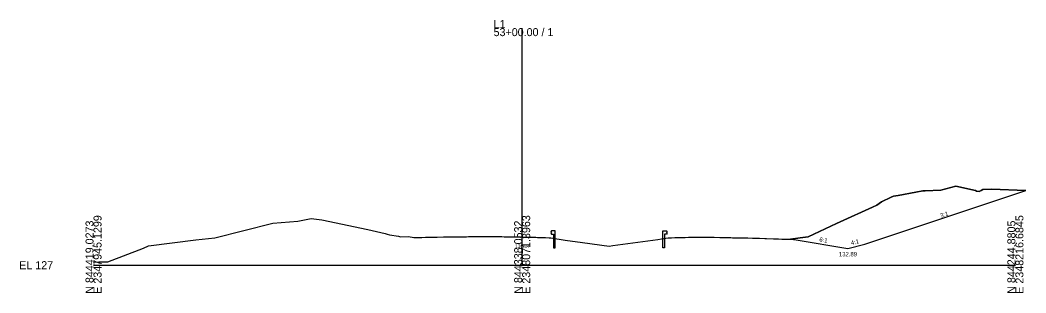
# Model space of a CAD drawing. Extents: x -26 to 2348258, y -10 to 844496.
# Drawn here: x 1275.5 to 1627.5, y 3990.3 to 4085.7 of the extents above; entities that cross this region are included whole.
import ezdxf

# ---------------------------------------------------------------- set-up
doc = ezdxf.new("R2010")
doc.units = 0
for name, color, linetype in [('Exist Cross Section Cell', 7, 'Continuous'), ('Exist XS Center Line Elevation Label', 7, 'Continuous'), ('Exist XS Ground Line', 7, 'Continuous'), ('Prop CMT Guardrail Graphics', 7, 'Continuous'), ('Prop CMT Slope Grass', 7, 'Continuous'), ('Prop XS Earthwork Shape', 7, 'Continuous'), ('Prop XS SE Text', 7, 'Continuous')]:
    doc.layers.add(name, color=color, linetype=linetype)

msp = doc.modelspace()

# ---------------------------------------------------------------- linework, layer by layer
at = {"layer": 'Exist Cross Section Cell'}
for p, q in [((1451.19, 4000), (1451.19, 4082.94)), ((1301.19, 4000), (1451.19, 4000)), ((1451.19, 4000), (1623.79, 4000))]:
    msp.add_line(p, q, dxfattribs=at)
at = {"layer": 'Exist XS Ground Line'}
msp.add_lwpolyline([(1301.19, 4001.09), (1303, 4001.15), (1306.15, 4001.18), (1318.67, 4006), (1320.44, 4006.74), (1336.99, 4008.9), (1343.58, 4009.57), (1363.88, 4014.68), (1372.69, 4015.36), (1377.35, 4016.29), (1381.14, 4015.87), (1397.17, 4012.49), (1403.26, 4011.09), (1403.9, 4010.82), (1404.74, 4010.63), (1407.87, 4010.12), (1408.59, 4009.97), (1411.37, 4010.03), (1413.3, 4009.69), (1414.66, 4009.71), (1416.02, 4009.74), (1417.33, 4009.77), (1417.8, 4009.78), (1418.52, 4009.79), (1420.36, 4009.82), (1421.44, 4009.84), (1423.61, 4009.88), (1426.26, 4009.91), (1427.38, 4009.91), (1428.47, 4009.94), (1429.21, 4009.95), (1431.76, 4009.97), (1432.41, 4009.98), (1434.09, 4009.99), (1435.17, 4010), (1435.91, 4010.01), (1437.06, 4010.02), (1438.36, 4010.02), (1439.68, 4010.02), (1441.27, 4010.01), (1441.61, 4010.01), (1443.08, 4009.99), (1444.05, 4009.98), (1444.92, 4009.97), (1446.27, 4009.95), (1447.01, 4009.94), (1448.32, 4009.91), (1449.98, 4009.88), (1450.57, 4009.86), (1451.19, 4009.84), (1451.94, 4009.83), (1452.95, 4009.81), (1453.96, 4009.8), (1455.93, 4009.75), (1456.54, 4009.73), (1458.84, 4009.66), (1459.39, 4009.63), (1460.68, 4009.57), (1461.2, 4009.56), (1466.18, 4008.75), (1472.29, 4007.93), (1481.62, 4006.68), (1482.91, 4006.85), (1498.62, 4009), (1499.98, 4009.22), (1502.25, 4009.57), (1503.08, 4009.58), (1503.47, 4009.6), (1504.66, 4009.66), (1506.51, 4009.7), (1508.28, 4009.73), (1509.42, 4009.76), (1510.13, 4009.77), (1511.19, 4009.78), (1512.4, 4009.79), (1512.76, 4009.8), (1514.98, 4009.79), (1515.77, 4009.79), (1518.34, 4009.76), (1520.41, 4009.72), (1521.31, 4009.71), (1522.9, 4009.67), (1524.23, 4009.65), (1524.81, 4009.62), (1525.58, 4009.61), (1527.24, 4009.58), (1529.57, 4009.53), (1530.15, 4009.52), (1531.74, 4009.48), (1533.14, 4009.45), (1533.59, 4009.44), (1534.26, 4009.42), (1536.1, 4009.36), (1536.69, 4009.35), (1539.12, 4009.25), (1540.92, 4009.19), (1542.06, 4009.15), (1543.52, 4009.1), (1545.1, 4009.05), (1548.52, 4009.55), (1551.25, 4009.94), (1561.24, 4014.6), (1562.48, 4015.18), (1573.76, 4020.32), (1575.3, 4021.02), (1576.9, 4022.11), (1580.35, 4023.8), (1581.14, 4024.17), (1582.76, 4024.4), (1588.96, 4025.56), (1591.35, 4025.96), (1592.21, 4025.97), (1597.7, 4026.19), (1602.95, 4027.65), (1609.85, 4026.1), (1610.19, 4025.94), (1611.11, 4025.77), (1611.76, 4026.17), (1612.36, 4026.48), (1615.37, 4026.6), (1627.46, 4026.18)], dxfattribs=at)
at = {"layer": 'Prop CMT Guardrail Graphics'}
for p, q in [((1461.46, 4012.06), (1461.19, 4011.77)), ((1461.19, 4011.77), (1461.46, 4011.48)), ((1461.46, 4011.48), (1461.19, 4011.19)), ((1461.19, 4011.19), (1461.46, 4010.9)), ((1462.79, 4012.06), (1461.46, 4012.06)), ((1461.46, 4010.9), (1462.13, 4010.9)), ((1462.13, 4010.9), (1462.13, 4006.06)), ((1462.79, 4006.06), (1462.79, 4012.06)), ((1500.38, 4006.03), (1500.38, 4012.03)), ((1500.38, 4012.03), (1501.71, 4012.03)), ((1501.71, 4010.86), (1501.04, 4010.86)), ((1501.04, 4010.86), (1501.04, 4006.03)), ((1501.71, 4012.03), (1501.98, 4011.74)), ((1501.98, 4011.74), (1501.71, 4011.44)), ((1501.71, 4011.44), (1501.98, 4011.15)), ((1501.98, 4011.15), (1501.71, 4010.86)), ((1462.13, 4006.06), (1462.79, 4006.06)), ((1501.04, 4006.03), (1500.38, 4006.03))]:
    msp.add_line(p, q, dxfattribs=at)
at = {"layer": 'Prop CMT Slope Grass'}
for p, q in [((1571.1, 4007.39), (1627.46, 4026.18)), ((1545.1, 4009.05), (1547.1, 4008.89)), ((1547.1, 4008.89), (1565.1, 4005.89)), ((1565.1, 4005.89), (1571.1, 4007.39))]:
    msp.add_line(p, q, dxfattribs=at)
at = {"layer": 'Prop XS Earthwork Shape'}
msp.add_lwpolyline([(1545.1, 4009.05), (1547.1, 4008.89), (1565.1, 4005.89), (1571.1, 4007.39), (1627.46, 4026.18), (1615.37, 4026.6), (1612.36, 4026.48), (1611.76, 4026.17), (1611.11, 4025.77), (1610.19, 4025.94), (1609.85, 4026.1), (1602.95, 4027.65), (1597.7, 4026.19), (1592.21, 4025.97), (1591.35, 4025.96), (1588.96, 4025.56), (1582.76, 4024.4), (1581.14, 4024.17), (1580.35, 4023.8), (1576.9, 4022.11), (1575.3, 4021.02), (1573.76, 4020.32), (1562.48, 4015.18), (1561.24, 4014.6), (1551.25, 4009.94), (1548.52, 4009.55)], close=True, dxfattribs=at)

# ---------------------------------------------------------------- texts
at = {"layer": 'Exist Cross Section Cell'}
for s, p in [('53+00.00 / 1', (1441.19, 4080.14)), ('L1', (1441.19, 4082.94)), ('EL 127', (1275.19, 3998.6))]:
    msp.add_text(s, height=2.8, dxfattribs=at).set_placement(p)
for s, p in [('E 2347945.1299', (1303.99, 3990)), ('E 2348071.3963', (1453.99, 3990)), ('E 2348216.6845', (1626.59, 3990)), ('N 844419.0273', (1301.19, 3990)), ('N 844338.0532', (1451.19, 3990)), ('N 844244.8805', (1623.79, 3990))]:
    msp.add_text(s, height=2.8, rotation=90, dxfattribs=at).set_placement(p)
at = {"layer": 'Exist XS Center Line Elevation Label'}
msp.add_text('136.84', height=1.2, dxfattribs=at).set_placement((1448.72, 4006.05))
at = {"layer": 'Prop XS SE Text'}
for s, rotation, p in [('3:1', 18.4349, (1597.74, 4016.57)), ('6:1', 350.5377, (1555.09, 4008.3)), ('4:1', 14.0362, (1566.41, 4007.02))]:
    msp.add_text(s, height=1.5, rotation=rotation, dxfattribs=at).set_placement(p)
msp.add_text('132.89', height=1.5, dxfattribs=at).set_placement((1562.03, 4003.1))

doc.saveas('drawing.dxf')
